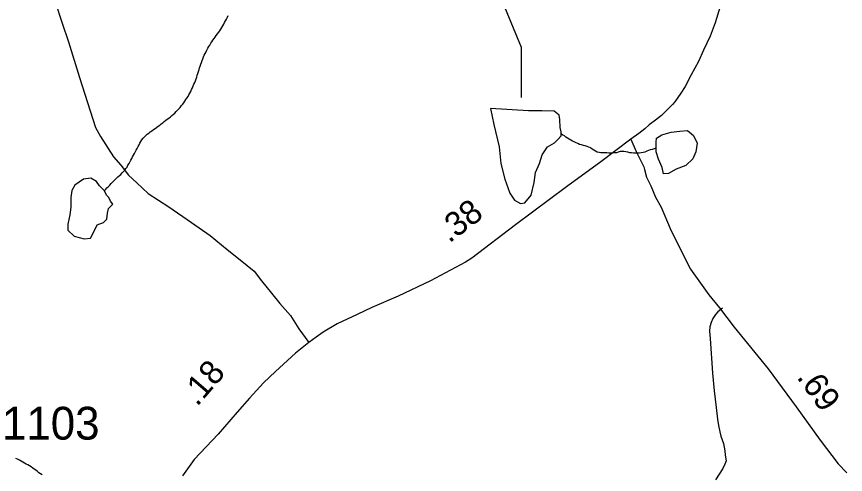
# Model space of a CAD drawing. Extents: x 1950930 to 2061844, y 904556 to 1017002.
# Drawn here: x 1978977 to 1983271, y 911569 to 913941 of the extents above; entities that cross this region are included whole.
import ezdxf

# ---------------------------------------------------------------- set-up
doc = ezdxf.new("R2010")
doc.units = 0
for name, color, linetype in [('Exist Hydrographic Creek Single Shore', 7, 'Continuous'), ('Exist Hydrographic Misc Water Feature', 7, 'Continuous'), ('Exist Road Non-System Type 51', 7, 'Continuous'), ('Exist Road Primary US Structure Standard Bridge CELL', 7, 'Continuous'), ('Exist Road Secondary Type 51 Attributed', 7, 'Continuous'), ('Exist Road Secondary Type 51 Number Label', 7, 'Continuous')]:
    doc.layers.add(name, color=color, linetype=linetype)

msp = doc.modelspace()

# ---------------------------------------------------------------- linework, layer by layer
at = {"layer": 'Exist Hydrographic Creek Single Shore'}
for points in [[(1981593.1, 913521.8), (1981593.1, 913781), (1981052, 915088.5), (1981036, 915272.7), (1981119, 915454.8), (1981119, 915612.3), (1980803, 916189.8), (1980619.9, 916731.9), (1980327.9, 917154.6), (1980319.9, 917322.2), (1980429, 917779.4)], [(1980000.1, 913826.3), (1980006.3, 913834.7), (1980011.8, 913842.8), (1980018.4, 913850.7), (1980023.9, 913858.8), (1980029.9, 913866.8), (1980035.2, 913875.7), (1980040.5, 913883.9), (1980045.7, 913892.8), (1980050.2, 913901.9), (1980054.9, 913909.8), (1980059.8, 913918.7), (1980064.7, 913927.7), (1980069.7, 913936.7), (1980074, 913945.3)], [(1979431.7, 913039), (1979438.9, 913046.4), (1979445.7, 913053.6), (1979452.9, 913060.5), (1979459.6, 913068), (1979466.8, 913075.5), (1979473.4, 913082.6), (1979480.5, 913089.6), (1979487.7, 913096.2), (1979494.7, 913103.3), (1979502.3, 913110.7), (1979509.9, 913117.2), (1979517.2, 913123.4), (1979524.4, 913130.5), (1979531.2, 913137.9), (1979537.7, 913145), (1979543.9, 913153), (1979549.4, 913161.1), (1979554.4, 913170.5), (1979559.7, 913179.1), (1979564.4, 913187.3), (1979569.7, 913196.2), (1979574.2, 913205.2), (1979578.6, 913213.9), (1979583.1, 913222.9), (1979588, 913232), (1979592.5, 913241), (1979597.6, 913249.2), (1979602.5, 913257.8), (1979607.1, 913267.6), (1979611.6, 913276.7), (1979616.5, 913285.7), (1979621.6, 913293.4), (1979626.9, 913302.3), (1979632.9, 913310), (1979639.7, 913317.1), (1979646.6, 913324.1), (1979654.2, 913330.7), (1979661.6, 913337.2), (1979670, 913343.7), (1979677.6, 913349), (1979686, 913355.5), (1979694.4, 913361), (1979702.2, 913366.8), (1979710.8, 913372.3), (1979718.6, 913378.5), (1979727, 913384.9), (1979734.2, 913390.7), (1979742.6, 913396.7), (1979750.4, 913403.3), (1979758.2, 913409), (1979766, 913415.1), (1979774.4, 913421.5), (1979781.8, 913428.1), (1979789.6, 913434.6), (1979796.9, 913440.8), (1979803.9, 913448.3), (1979810.9, 913455.4), (1979817.6, 913462.8), (1979824.4, 913469.9), (1979830.8, 913477.9), (1979837.1, 913485.1), (1979843.3, 913493.5), (1979849, 913502.3), (1979854.6, 913510.4), (1979859.7, 913518.5), (1979865.4, 913527.4), (1979870.1, 913535.6), (1979875.1, 913544.2), (1979879.6, 913553.3), (1979884.1, 913562.3), (1979888, 913571), (1979892.3, 913581), (1979896.2, 913589.7), (1979899.9, 913598.9), (1979904, 913608.4), (1979907.3, 913617.7), (1979910.5, 913627.3), (1979913.4, 913637), (1979916.3, 913646), (1979919.1, 913655.6), (1979922.4, 913665.6), (1979925.3, 913674.6), (1979928.6, 913684.2), (1979931.9, 913694.2), (1979935.1, 913703.1), (1979938.4, 913712.7), (1979942.1, 913721.9), (1979945.8, 913731.5), (1979949.9, 913740.6), (1979954.2, 913749.3), (1979958.7, 913758.3), (1979963.6, 913767.3), (1979968.2, 913776.4), (1979973.5, 913785.3), (1979978.2, 913793.2), (1979983.5, 913802.1), (1979989.1, 913810.1), (1979994.2, 913818.3), (1980000.1, 913826.3)], [(1979109, 911566.2), (1979100.6, 911572.4), (1979092.6, 911578), (1979084.8, 911584.9), (1979077, 911591), (1979068.4, 911595.9), (1979060.6, 911602), (1979052.2, 911607.7), (1979043.6, 911613.1), (1979035.2, 911618.1), (1979026.6, 911623), (1979018.1, 911627.9), (1979009.3, 911633.4), (1979000.7, 911638.3), (1978992.1, 911642.8), (1978982.7, 911647.9), (1978974.1, 911652.1)]]:
    msp.add_lwpolyline(points, dxfattribs=at)
at = {"layer": 'Exist Hydrographic Misc Water Feature'}
for points in [[(1981628.7, 913451.7), (1981432, 913464.5), (1981449, 913380.8), (1981477.3, 913265.3), (1981486.2, 913180.3), (1981506.7, 913098.9), (1981533.5, 913025.5), (1981557.7, 912989.7), (1981587.9, 912971.7), (1981609.8, 912976), (1981643.6, 913015.6), (1981658.8, 913081.9), (1981666.4, 913132.6), (1981686.3, 913180.4), (1981700, 913224.5), (1981727.9, 913266.5), (1981763.6, 913287.1), (1981781, 913304.7), (1981799.1, 913323.5), (1981798.9, 913333.2)], [(1981798.9, 913333.2), (1981799.3, 913343), (1981792.7, 913365.4), (1981792.5, 913407.3), (1981788.2, 913429.4), (1981762.2, 913451.3), (1981698.2, 913452.5), (1981628.7, 913451.7)], [(1982291.6, 913258.3), (1982279.7, 913255.2), (1982269.9, 913252.7), (1982260.6, 913250.1), (1982250.6, 913246.7), (1982242, 913242.7), (1982232.7, 913238.9), (1982222.9, 913236), (1982213.3, 913234.5), (1982203.2, 913232.8), (1982193, 913232.4), (1982183.3, 913232.6), (1982173.3, 913233.7), (1982163.2, 913234.4), (1982153.6, 913235.5), (1982143.3, 913238.2), (1982133.9, 913240.1), (1982123.9, 913241.2), (1982114, 913242.3), (1982104, 913241.4), (1982094.1, 913238.4), (1982084.7, 913235.4), (1982075.1, 913234), (1982065.2, 913232.7), (1982055, 913232.7), (1982045.1, 913232.9), (1982035.3, 913234), (1982024.6, 913234.4), (1982014.8, 913234.3), (1982004.5, 913235.4), (1981994.9, 913236.5), (1981985.5, 913239.1), (1981976.2, 913242.6), (1981967.8, 913248.3), (1981960, 913254.4), (1981951.2, 913260.1), (1981942.6, 913264.4), (1981933, 913268.2), (1981923.3, 913270.9), (1981913.9, 913273.2), (1981903.6, 913275.9), (1981894.4, 913278.6), (1981885.4, 913283.2), (1981876.2, 913286.6), (1981866.7, 913291.7), (1981858.1, 913295.8), (1981849.5, 913300.7), (1981840.7, 913306.2), (1981832.3, 913311.1), (1981823.7, 913316.1), (1981815.7, 913322.2), (1981807.3, 913327.1), (1981798.9, 913333.2)], [(1982291.6, 913258.3), (1982291.4, 913271.3), (1982291.2, 913290.9), (1982293.2, 913310.9), (1982321.1, 913327.3), (1982368.9, 913342), (1982412.8, 913347.5), (1982452.8, 913349.9), (1982485, 913324.7), (1982503.4, 913284.1), (1982495.6, 913240.7), (1982481.5, 913204.3), (1982444.4, 913169.8), (1982394.1, 913149.4), (1982354.3, 913127.5), (1982328.5, 913125.3), (1982322.4, 913159.2), (1982302.3, 913201.5), (1982291.4, 913239.2), (1982291.6, 913258.3)], [(1979431.7, 913039), (1979407.7, 913063.3), (1979391.5, 913086.5), (1979361.2, 913102.9), (1979323.1, 913098.6), (1979279.8, 913067.8), (1979264, 913040.1), (1979258.1, 913004.1), (1979258.7, 912954.1), (1979252.9, 912914), (1979243.1, 912865.6), (1979243.3, 912833.9), (1979275.7, 912803.4), (1979327.8, 912790.2), (1979359.8, 912792.6), (1979379.7, 912828.6), (1979395.2, 912861.1), (1979427, 912873.3), (1979444.9, 912891), (1979448.8, 912921.6), (1979452.7, 912947.3), (1979476.6, 912969.3), (1979463.9, 912985), (1979455.9, 913003.2), (1979444, 913013.2), (1979431.7, 913039)]]:
    msp.add_lwpolyline(points, dxfattribs=at)
at = {"layer": 'Exist Road Non-System Type 51'}
msp.add_lwpolyline([(1982634, 912430.9), (1982610, 912411.1), (1982597.5, 912397.4), (1982584.9, 912376.4), (1982576.5, 912355.5), (1982569.1, 912333.4), (1982568, 912311.4), (1982570.1, 912272.6), (1982582.8, 912093.2), (1982591.1, 912001.9), (1982595.9, 911959.4), (1982601.1, 911916.4), (1982609.5, 911855.6), (1982613.8, 911823), (1982620, 911789.4), (1982626.2, 911767.4), (1982640.5, 911729.1), (1982646.8, 911691.4), (1982648.9, 911668.2), (1982653, 911638.9), (1982646.8, 911622.1), (1982636.2, 911599), (1982617.4, 911570.7), (1982598.5, 911541.3)], dxfattribs=at)
at = {"layer": 'Exist Road Secondary Type 51 Attributed'}
for points in [[(1979176.9, 914016.7), (1979213, 913906.9), (1979245.7, 913810.4), (1979303, 913624.7), (1979386.5, 913365.6), (1979412.3, 913320), (1979479.1, 913214.4), (1979516.7, 913171.4), (1979557.7, 913119.8), (1979600.9, 913079.5), (1979659.8, 913024.4), (1979765.3, 912954.5), (1979884, 912873.6), (1979980.2, 912805.8), (1980068.4, 912734), (1980136.4, 912680), (1980207.9, 912622.5), (1980246.5, 912572.3), (1980298.6, 912508.3), (1980340.8, 912454.4), (1980396.5, 912391.9), (1980439, 912323.5), (1980491, 912252.5)], [(1982622.1, 913992.7), (1982596.2, 913908.6), (1982570.3, 913838.4), (1982536.6, 913766.5), (1982510.6, 913708.3), (1982472.7, 913638.3), (1982440.8, 913578.3), (1982418.8, 913544.4), (1982386.9, 913498.3), (1982376.2, 913485.8), (1982318.5, 913428.1), (1982286.6, 913403.8), (1982254.7, 913380.2), (1982231.5, 913358.6), (1982201.2, 913335.8), (1982160.2, 913306.1)], [(1982160.2, 913306.1), (1982003.4, 913188.8), (1981826.6, 913058.8), (1981562, 912861.7), (1981335.2, 912688.6), (1981302.6, 912668.1), (1981121.5, 912571.2), (1980953.4, 912491.8), (1980817.1, 912434.4), (1980741.9, 912398), (1980637.6, 912349.7), (1980566.2, 912305.7), (1980529.8, 912279.8), (1980491, 912252.5)], [(1982160.2, 913306.1), (1982186.8, 913241.6), (1982226.6, 913162.9), (1982229.6, 913149.2), (1982240.3, 913109), (1982263.8, 913063.4), (1982287.2, 913005.7), (1982316, 912954.1), (1982363.1, 912843.1), (1982413.2, 912741.3), (1982468.2, 912632.3), (1982564.3, 912499), (1982618.9, 912432.1), (1982695.6, 912332.6), (1982871.7, 912115.3), (1983016, 911919.3), (1983141.2, 911746.8), (1983233.8, 911623.7), (1983277.9, 911576.6)], [(1980491, 912252.5), (1980422.7, 912197.8), (1980318.3, 912102.4), (1980256.8, 912043.9), (1980183.6, 911963.7), (1980120.6, 911890.8), (1980021.5, 911778), (1979897, 911646.5), (1979836.6, 911561.8)]]:
    msp.add_lwpolyline(points, dxfattribs=at)

# ---------------------------------------------------------------- texts
at = {"layer": 'Exist Road Primary US Structure Standard Bridge CELL'}
for s, rotation, p in [('.38', 37.349, (1981218.7, 912764.3)), ('.18', 49.1777, (1979912.3, 911917.3)), ('.69', 305.9892, (1983015.8, 912072.3))]:
    msp.add_text(s, height=125, rotation=rotation, dxfattribs=at).set_placement(p)
at = {"layer": 'Exist Road Secondary Type 51 Number Label'}
msp.add_text('1103', height=170, dxfattribs=at).set_placement((1978901.4, 911749.4))

doc.saveas('drawing.dxf')
